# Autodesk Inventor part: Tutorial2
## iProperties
Shininess: 77.0
Length Units: 11269
Angle Units: 11279
Time Units: 11290
Mass Units: 11283
Length Display Precision: 3
Angle Display Precision: 2
Created: 2001-11
Part Number: Tutorial2
Document SubType Name: Modeling
Designer: Renu Muthoo
Density: 1 g/cm^3
Density: 0.0
Volumn: 0.0
Area: 0.0
PropertySet Name: Model Information
Control State: 0
Master: False
Checked Out: False
Author: Renu Muthoo
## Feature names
1. Extrusion1
2. Extrusion2
3. Extrusion3
4. Extrusion4
5. Extrusion5
